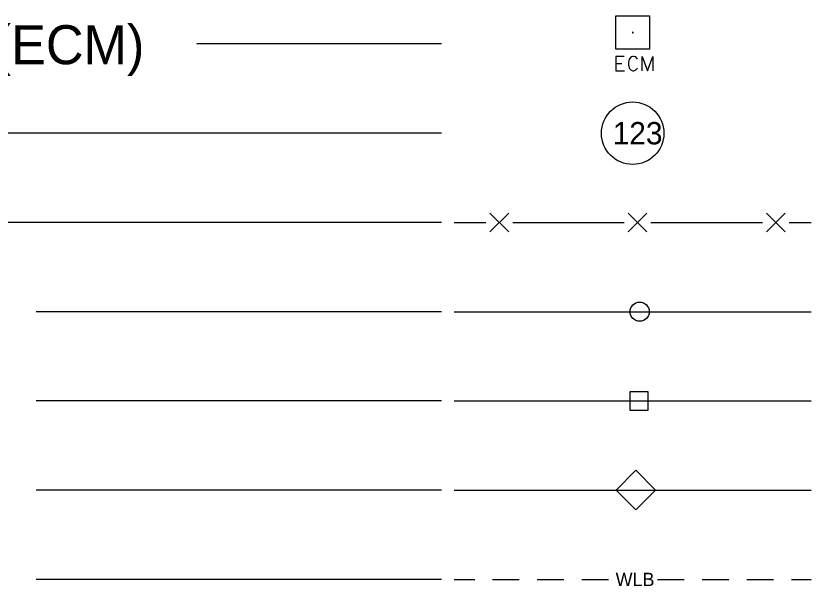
# Model space of a CAD drawing. Extents: x 811137 to 813186, y 647386 to 648494.
# Drawn here: x 811361.2 to 811541.1, y 648094.9 to 648223.8 of the extents above; entities that cross this region are included whole.
import ezdxf

# ---------------------------------------------------------------- set-up
doc = ezdxf.new("R2010")
doc.units = 0
doc.layers.add('Sheet_Symbology', color=7, linetype='Continuous')

msp = doc.modelspace()

# ---------------------------------------------------------------- linework, layer by layer
at = {"layer": 'Sheet_Symbology'}
for p, q in [((811457.46, 648217.48), (811402.14, 648217.48)), ((811496.91, 648213.04), (811498.23, 648213.04)), ((811457.46, 648197.3), (811356.07, 648197.3)), ((811468.43, 648175), (811472.67, 648179.24)), ((811472.67, 648175), (811468.43, 648179.24)), ((811499.71, 648175), (811503.94, 648179.24)), ((811503.94, 648175), (811499.71, 648179.24)), ((811530.98, 648175), (811535.22, 648179.24)), ((811535.22, 648175), (811530.98, 648179.24)), ((811457.46, 648177.12), (811311.05, 648177.12)), ((811460.36, 648177.12), (811467.52, 648177.12)), ((811473.57, 648177.12), (811486.19, 648177.12)), ((811486.19, 648177.12), (811498.8, 648177.12)), ((811504.85, 648177.12), (811517.46, 648177.12)), ((811517.46, 648177.12), (811530.07, 648177.12)), ((811536.13, 648177.12), (811541.07, 648177.12)), ((811457.46, 648156.94), (811365.81, 648156.94)), ((811460.36, 648156.94), (811541.07, 648156.94)), ((811460.36, 648156.94), (811541.07, 648156.94)), ((811457.46, 648136.77), (811365.81, 648136.77)), ((811460.36, 648136.77), (811541.07, 648136.77)), ((811460.36, 648136.77), (811541.07, 648136.77)), ((811457.46, 648116.59), (811365.81, 648116.59)), ((811460.36, 648116.59), (811541.07, 648116.59)), ((811460.36, 648116.59), (811541.07, 648116.59)), ((811457.46, 648096.41), (811365.81, 648096.41)), ((811460.36, 648096.41), (811464.97, 648096.41)), ((811469.01, 648096.41), (811475.06, 648096.41)), ((811479.1, 648096.41), (811485.15, 648096.41)), ((811489.19, 648096.41), (811495.24, 648096.41)), ((811506.34, 648096.41), (811512.39, 648096.41)), ((811516.43, 648096.41), (811522.48, 648096.41)), ((811526.52, 648096.41), (811532.57, 648096.41)), ((811536.61, 648096.41), (811541.07, 648096.41))]:
    msp.add_line(p, q, dxfattribs=at)
for points in [[(811496.93, 648223.83), (811504.49, 648223.83), (811504.49, 648216.27), (811496.93, 648216.27), (811496.93, 648223.83)], [(811500.69, 648220.14), (811500.65, 648220.1), (811500.65, 648220.03), (811500.73, 648219.95), (811500.8, 648219.99), (811500.84, 648220.07), (811500.76, 648220.14), (811500.69, 648220.14)], [(811498.76, 648214.64), (811496.91, 648214.64), (811496.91, 648211.41), (811498.89, 648211.41)], [(811501.81, 648214.01), (811501.41, 648214.54), (811501, 648214.64), (811500.72, 648214.64), (811500.34, 648214.54), (811499.91, 648214.01), (811499.8, 648213.3), (811499.8, 648212.91), (811499.8, 648212.66), (811499.83, 648212.43), (811499.91, 648212.02), (811500.34, 648211.52), (811500.72, 648211.41), (811500.95, 648211.41), (811501.38, 648211.52), (811501.81, 648212.02)], [(811502.85, 648211.41), (811502.85, 648214.64), (811504.07, 648211.41), (811505.24, 648214.64), (811505.24, 648211.41)]]:
    msp.add_lwpolyline(points, dxfattribs=at)
for points in [[(811500.08, 648134.7), (811504.22, 648134.7), (811504.22, 648138.83), (811500.08, 648138.83)], [(811501.42, 648112.15), (811505.86, 648116.59), (811501.42, 648121.08), (811496.98, 648116.59)]]:
    msp.add_lwpolyline(points, close=True, dxfattribs=at)
for centre, radius in [((811500.71, 648197.3), 7.06), ((811502.3, 648156.94), 2.17)]:
    msp.add_circle(centre, radius, dxfattribs=at)

# ---------------------------------------------------------------- texts
for s, height, p in [('Existing Concrete Monument (ECM)', 8.8282, (811201.31, 648212.9)), ('123', 5.045, (811496.2, 648194.78)), ('WLB', 3.027, (811496.86, 648094.89))]:
    msp.add_text(s, height=height, dxfattribs=at).set_placement(p)

doc.saveas('drawing.dxf')
